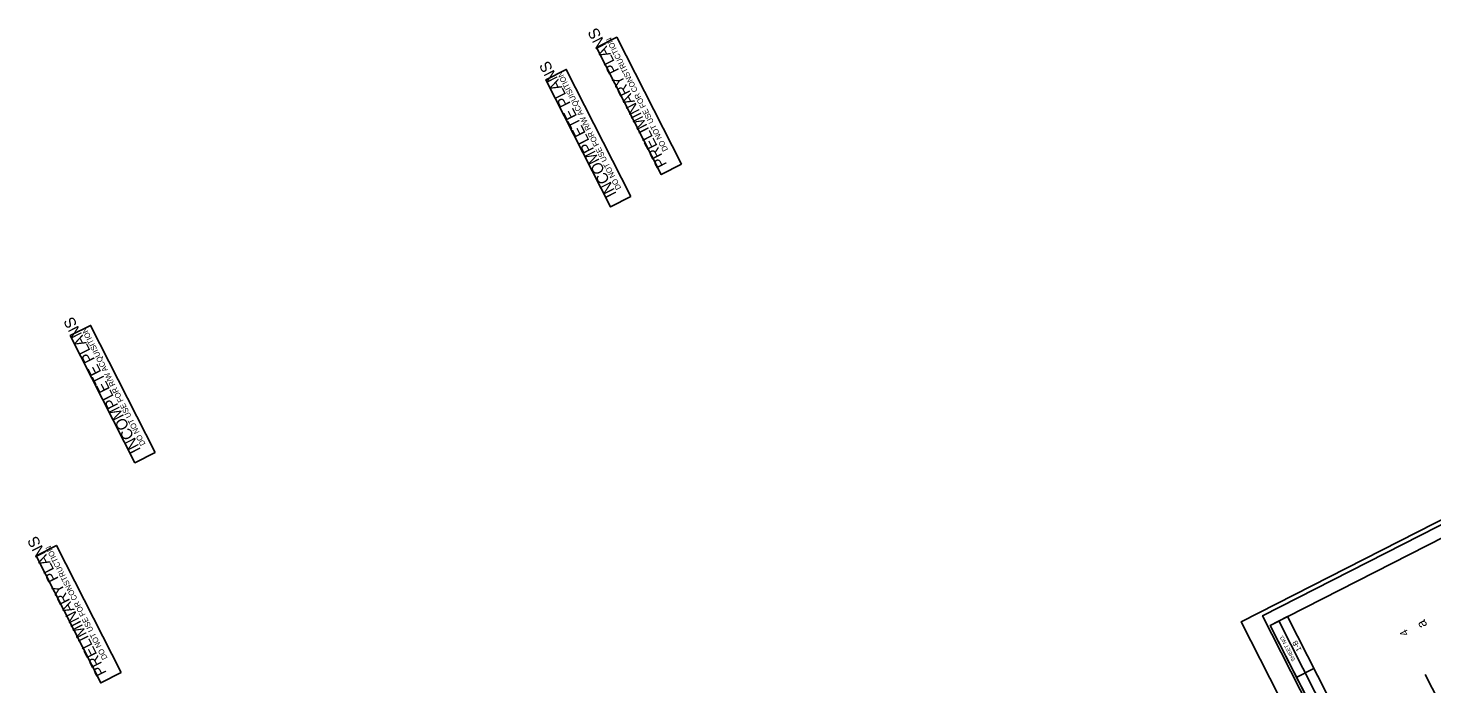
# Model space of a CAD drawing. Extents: x 558484 to 564063, y 513718 to 518374.
# Drawn here: x 558484 to 559932, y 516446 to 517121 of the extents above; entities that cross this region are included whole.
import ezdxf

# ---------------------------------------------------------------- set-up
doc = ezdxf.new("R2010")
doc.units = 0
for name, color, linetype in [('Sheet Cutting Line CELL', 7, 'Continuous'), ('Sheet Data Field CELL', 7, 'Continuous'), ('Sheet Plot Border Inside CELL', 7, 'Continuous'), ('Sheet Plot Border Outside CELL', 7, 'Continuous'), ('Sheet Sticker Incomplete CELL', 7, 'Continuous'), ('Sheet Sticker Preliminary CELL', 7, 'Continuous'), ('Sheet Symbology CELL', 7, 'Continuous')]:
    doc.layers.add(name, color=color, linetype=linetype)

msp = doc.modelspace()

# ---------------------------------------------------------------- linework, layer by layer
at = {"layer": 'Sheet Cutting Line CELL'}
msp.add_line((559735.1, 516509.6), (560499.1, 515008.9), dxfattribs=at)
at = {"layer": 'Sheet Plot Border Inside CELL'}
msp.add_lwpolyline([(561453.5, 515509.4), (560697.4, 516994.5), (559757.1, 516515.8), (560513.2, 515030.7)], close=True, dxfattribs=at)
at = {"layer": 'Sheet Plot Border Outside CELL'}
msp.add_lwpolyline([(561479.4, 515508), (560715.3, 517008.7), (559735.1, 516509.6), (560499.1, 515008.9)], close=True, dxfattribs=at)
at = {"layer": 'Sheet Sticker Incomplete CELL'}
for points in [[(559105.8, 516947.9), (559084.9, 516937.2), (559018.2, 517068.2), (559039.1, 517078.9)], [(558615.3, 516684.1), (558594.4, 516673.5), (558527.7, 516804.5), (558548.6, 516815.1)]]:
    msp.add_lwpolyline(points, close=True, dxfattribs=at)
at = {"layer": 'Sheet Sticker Preliminary CELL'}
for points in [[(559157.9, 516981.1), (559137, 516970.5), (559070.3, 517101.5), (559091.2, 517112.1)], [(558580.1, 516457.2), (558559.1, 516446.5), (558492.4, 516577.5), (558513.4, 516588.2)]]:
    msp.add_lwpolyline(points, close=True, dxfattribs=at)
at = {"layer": 'Sheet Symbology CELL'}
for p, q in [((559846.6, 516367.8), (559774, 516510.4)), ((559855.5, 516372.3), (559782.9, 516514.9)), ((559792.3, 516452.4), (559810.1, 516461.4)), ((559924.8, 516455.4), (559998.5, 516310.7))]:
    msp.add_line(p, q, dxfattribs=at)
for points in [[(559765.1, 516505.8), (560445.6, 515169.1), (561380.4, 515645), (560699.9, 516981.8)], [(559837.7, 516363.2), (559765.1, 516505.8), (559782.9, 516514.9), (559855.5, 516372.3)]]:
    msp.add_lwpolyline(points, close=True, dxfattribs=at)

# ---------------------------------------------------------------- texts
at = {"layer": 'Sheet Data Field CELL'}
msp.add_text('1-B', height=5.4, rotation=116.9819, dxfattribs=at).set_placement((559797.5, 516480.6))
at = {"layer": 'Sheet Sticker Incomplete CELL'}
for s, height, p in [('INCOMPLETE PLANS', 11.52, (559091.3, 516950.5)), ('DO NOT USE FOR R/W ACQUISITION', 5.76, (559096, 516956.6)), ('INCOMPLETE PLANS', 11.52, (558600.8, 516686.8)), ('DO NOT USE FOR R/W ACQUISITION', 5.76, (558605.5, 516692.8))]:
    msp.add_text(s, height=height, rotation=116.9819, dxfattribs=at).set_placement(p)
at = {"layer": 'Sheet Sticker Preliminary CELL'}
for s, height, p in [('PRELIMINARY PLANS', 11.52, (559143.2, 516980.9)), ('DO NOT USE FOR CONSTRUCTION', 5.76, (559144.2, 516996.1)), ('PRELIMINARY PLANS', 11.52, (558565.4, 516457)), ('DO NOT USE FOR CONSTRUCTION', 5.76, (558566.3, 516472.2))]:
    msp.add_text(s, height=height, rotation=116.9819, dxfattribs=at).set_placement(p)
at = {"layer": 'Sheet Symbology CELL'}
for s, height, p in [('a', 10.2, (559927.3, 516505.9)), ('SHEET NO.', 4, (559791.2, 516470)), ('4', 8.25, (559908.1, 516497.2))]:
    msp.add_text(s, height=height, rotation=116.9819, dxfattribs=at).set_placement(p)

doc.saveas('drawing.dxf')
